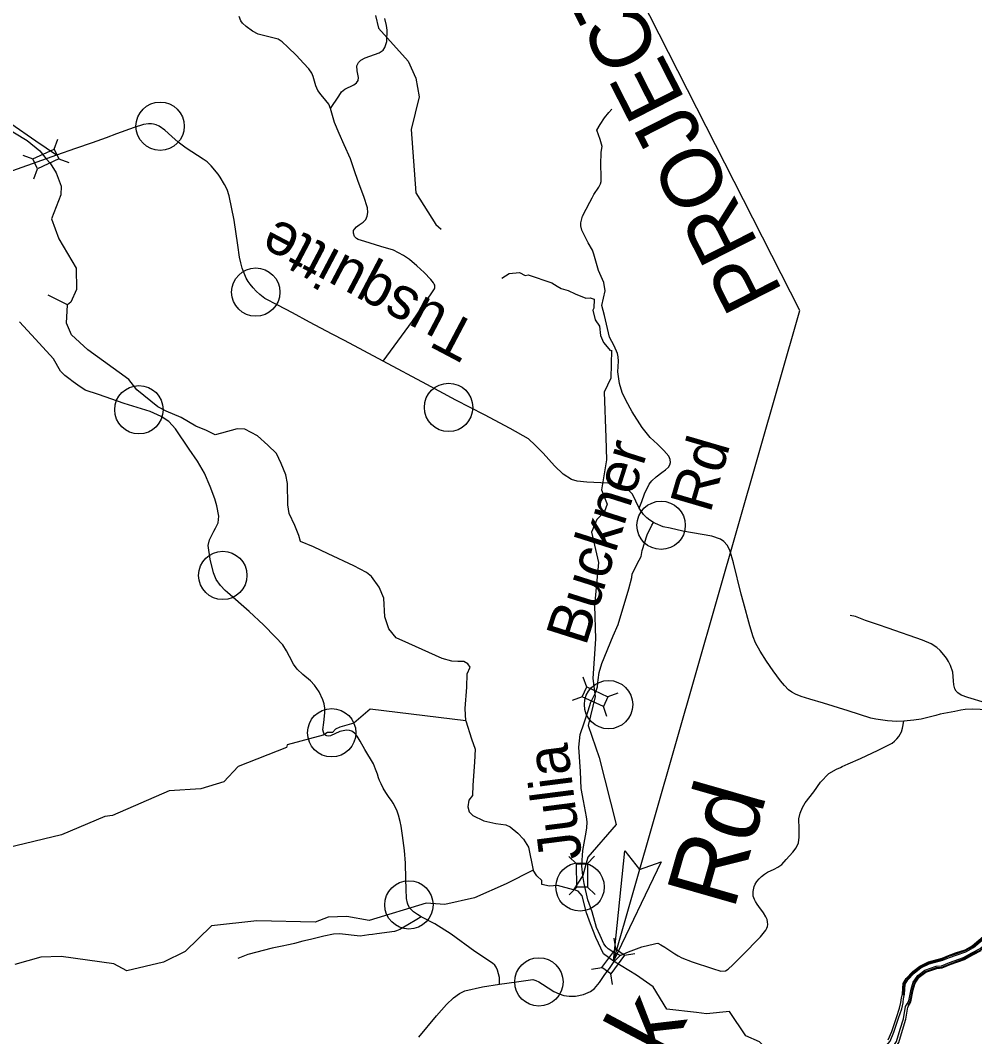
# Model space of a CAD drawing. Extents: x 558484 to 564063, y 513718 to 518374.
# Drawn here: x 559306.6 to 559464.9, y 514849.4 to 515017.9 of the extents above; entities that cross this region are included whole.
import ezdxf

# ---------------------------------------------------------------- set-up
doc = ezdxf.new("R2010")
doc.units = 0
for name, color, linetype in [('Default', 7, 'Continuous'), ('Prop Shade Heavy', 7, 'Continuous'), ('Prop Terminator CELL', 7, 'Continuous')]:
    doc.layers.add(name, color=color, linetype=linetype)

msp = doc.modelspace()

# ---------------------------------------------------------------- linework, layer by layer
at = {"layer": 'Default'}
for p, q in [((559312.23, 514996.58), (559312.84, 514998.24)), ((559312.6, 514995.58), (559298.66, 514990.63)), ((559307.06, 514995.55), (559308.72, 514994.94)), ((559312.98, 514994.97), (559314.64, 514994.37)), ((559308.88, 514991.64), (559309.49, 514993.31)), ((559314.47, 514970.78), (559311.23, 514972.37)), ((559400.56, 514907.37), (559399.95, 514909.03)), ((559399.81, 514905.77), (559398.15, 514905.16)), ((559405.74, 514906.37), (559404.08, 514905.77)), ((559403.92, 514902.47), (559403.32, 514904.13)), ((559398.86, 514878.05), (559397.59, 514879.29)), ((559400.63, 514878.07), (559401.86, 514879.34)), ((559399.9, 514876.13), (559398.36, 514873.77)), ((559397.66, 514872.91), (559398.89, 514874.18)), ((559401.97, 514872.96), (559400.7, 514874.2)), ((559405.38, 514864), (559405.11, 514865.75)), ((559406.81, 514862.95), (559408.56, 514863.22)), ((559401.34, 514860.61), (559403.09, 514860.88)), ((559404.81, 514858.06), (559404.55, 514859.81))]:
    msp.add_line(p, q, dxfattribs=at)
for points in [[(559358.09, 515003.29), (559357.81, 515004), (559357.3, 515004.65), (559356.54, 515005.55), (559355.95, 515006.27), (559355.61, 515007.04), (559355.18, 515008.59), (559354.94, 515009.18), (559354.48, 515009.9), (559353.61, 515010.84), (559352.41, 515012.1), (559351, 515013.48), (559350.05, 515014.35), (559349.36, 515014.79), (559346.05, 515015.65), (559345.15, 515016.12), (559344.1, 515016.89), (559343.45, 515017.44), (559343.18, 515017.86), (559342.91, 515018.58)], [(559365.55, 515018.72), (559366.04, 515016.65), (559370.93, 515011.14), (559372.24, 515008.31), (559372.75, 515005.26), (559371.45, 514999.82), (559372.21, 514989.32), (559375.53, 514984.1), (559376.41, 514983.31)], [(559295.85, 515017.9), (559296.77, 515015.43), (559296.56, 515011.17), (559296.9, 515009.3), (559297.78, 515007.14), (559298.85, 515005.69), (559303.22, 515000.72), (559307.74, 514998.01), (559309.87, 514996.27), (559310.89, 514994.94)], [(559358.09, 515003.29), (559359.42, 515005.34), (559359.87, 515006.08), (559360.45, 515006.5), (559361.95, 515007.25), (559362.4, 515007.56), (559362.67, 515007.95), (559362.69, 515008.45), (559362.48, 515009.53), (559362.44, 515010.36), (559362.68, 515010.93), (559363.12, 515011.32), (559363.83, 515011.71), (559366.11, 515012.53), (559366.77, 515012.99), (559367.06, 515013.42), (559367.38, 515014.41), (559367.46, 515016.32), (559367.34, 515017.06), (559367.05, 515018.25)], [(559366.81, 514961.41), (559371.68, 514968.03), (559374.89, 514972.77), (559375.29, 514973.43), (559375.35, 514973.59), (559375.38, 514973.74), (559375.38, 514973.88), (559375.36, 514974.03), (559375.28, 514974.2), (559375.17, 514974.4), (559374.7, 514974.98), (559373.6, 514976.1), (559372.39, 514977.22), (559371.16, 514978.25), (559370.19, 514978.95), (559368.49, 514979.83), (559366.39, 514980.45), (559363.74, 514981.24), (559362.66, 514981.6), (559362.35, 514981.76), (559362.06, 514982.08), (559361.86, 514982.65), (559361.9, 514983.08), (559362.03, 514983.31), (559362.36, 514983.66), (559362.82, 514984), (559363.5, 514984.46), (559363.91, 514984.9), (559364.15, 514985.43), (559364.24, 514986.04), (559364.19, 514986.84), (559363.59, 514988.74), (559362.63, 514991.2), (559361.98, 514993.16), (559361.37, 514994.95), (559360.35, 514997.28), (559359.52, 514999.14), (559358.72, 515001), (559358.09, 515003.29)], [(559401.45, 514988.51), (559401.73, 514989.07), (559402.58, 514990.25), (559402.87, 514990.81), (559402.94, 514991.2), (559402.93, 514992.09), (559402.88, 514993.98), (559402.93, 514996.09), (559403.1, 514997.01), (559402.79, 514998.19), (559402.23, 514999.71), (559402.78, 515000.63), (559403.49, 515001.74), (559404.2, 515002.62), (559404.7, 515003.22)], [(559312.6, 514995.58), (559309.17, 514997.9), (559305.04, 515000.79)], [(559366.81, 514961.41), (559360.37, 514964.86), (559358.32, 514965.91), (559354.56, 514967.89), (559351.77, 514969.41), (559349.34, 514970.7), (559347.17, 514971.82), (559346.35, 514972.47), (559345.75, 514973), (559345.25, 514973.56), (559344.74, 514974.16), (559344.41, 514974.61), (559344.08, 514975.16), (559343.87, 514975.71), (559343.41, 514976.81), (559343.18, 514977.7), (559342.97, 514978.68), (559342.68, 514980.65), (559342.09, 514984.77), (559341.27, 514988.84), (559340.91, 514989.86), (559340.47, 514990.7), (559339.79, 514991.92), (559339.42, 514992.43), (559338.26, 514993.81), (559337.6, 514994.44), (559336.95, 514994.93), (559334.14, 514996.73), (559332.82, 514997.71), (559331.73, 514998.69), (559330.57, 514999.74), (559329.65, 515000.37), (559329.13, 515000.61), (559328.7, 515000.73), (559328.36, 515000.78), (559327.88, 515000.74), (559327.06, 515000.64), (559325.51, 515000.18), (559322.55, 514999.09), (559320.84, 514998.47), (559318.51, 514997.64), (559315.78, 514996.65), (559312.6, 514995.58)], [(559310.89, 514994.94), (559311.58, 514994.25), (559312.58, 514992.64), (559313.42, 514990.42), (559313.36, 514988.99), (559311.78, 514985.01), (559312.98, 514981.68), (559315.87, 514976.83), (559315.93, 514973.29), (559315.02, 514971.17), (559314.47, 514970.78)], [(559409.28, 514937.06), (559409.69, 514938.12), (559410.13, 514939.44), (559410.94, 514941), (559411.38, 514941.55), (559412.06, 514942.23), (559412.99, 514942.93), (559413.64, 514943.4), (559414.11, 514943.84), (559414.32, 514944.2), (559414.43, 514944.6), (559414.38, 514945.11), (559414.15, 514945.67), (559413.37, 514946.6), (559412.27, 514947.63), (559411.1, 514948.76), (559409.77, 514950.44), (559408.11, 514953), (559407.05, 514954.92), (559406.42, 514956.22), (559405.97, 514957.73), (559405.71, 514959.65), (559405.82, 514961.44), (559405.8, 514962.15), (559405.66, 514962.67), (559405.09, 514963.96), (559404.32, 514965.4), (559403.49, 514968.96), (559403.07, 514970.64), (559403.59, 514973.09), (559403.41, 514974.47), (559402.53, 514976.44), (559401.72, 514979.15), (559401.51, 514979.84), (559400.77, 514981.05), (559399.72, 514983.12), (559399.56, 514983.85), (559399.6, 514984.37), (559399.86, 514985.46), (559401.09, 514987.79), (559401.45, 514988.51)], [(559386.49, 514975.15), (559387.71, 514975.95), (559389.4, 514976.09), (559390.33, 514975.63), (559390.82, 514975.74), (559394.79, 514974.38), (559395.65, 514973.85), (559396.31, 514973.46), (559397.47, 514973.14), (559398.62, 514972.59), (559400.41, 514971.86), (559401.12, 514971.92), (559401.77, 514971.68), (559401.74, 514970.22), (559401.55, 514969.85), (559401.98, 514968.26), (559402.69, 514967.21), (559402.86, 514965.67), (559403.32, 514964.49), (559404.48, 514963.15)], [(559325.96, 514956.68), (559324.63, 514958.37), (559317.81, 514963.29), (559315.12, 514965.79), (559314.3, 514967.71), (559314.47, 514970.78)], [(559350.79, 514913.4), (559350.13, 514914.38), (559348.96, 514915.64), (559346.93, 514917.72), (559344.56, 514919.89), (559340.97, 514923.05), (559340.57, 514923.39), (559339.82, 514924.22), (559339.11, 514925.2), (559338.67, 514926.34), (559338.1, 514928.59), (559337.79, 514930.87), (559338.02, 514931.81), (559338.72, 514933.23), (559339, 514933.73), (559339.44, 514934.63), (559339.53, 514935.7), (559339.21, 514937.45), (559338.89, 514938.57), (559338.08, 514940.64), (559337.16, 514942.87), (559335.99, 514944.81), (559334.62, 514946.81), (559332.33, 514950.19), (559331.24, 514951.43), (559330, 514952.26), (559328.13, 514953.09), (559323.83, 514954.37), (559319.6, 514955.91), (559317.36, 514956.63), (559316.18, 514957.43), (559315.38, 514958.01), (559314.69, 514958.53), (559313.99, 514959.06), (559313.28, 514959.76), (559312.11, 514961.78), (559310.37, 514963.76), (559308.46, 514965.79), (559306.51, 514967.92)], [(559404.68, 514963.22), (559404.54, 514958.62), (559403.46, 514956.28), (559403.71, 514948.78), (559403.83, 514945.03), (559403.03, 514940.1), (559403.97, 514937.68), (559403.53, 514936.48), (559402.23, 514935.18), (559401.36, 514933.08), (559402.5, 514928.02), (559401.86, 514920.88), (559402.01, 514915.39), (559401.57, 514908.77), (559401.94, 514905.84), (559400.78, 514901), (559402.63, 514895.7), (559405.43, 514884.57), (559400.76, 514879.15), (559399.9, 514876.13)], [(559409.28, 514937.06), (559408.14, 514939.35), (559407.32, 514940.2), (559406.67, 514940.66), (559405.5, 514941.1), (559404.06, 514941.19), (559400.56, 514941.33), (559398.98, 514941.54), (559398.01, 514941.8), (559396.67, 514942.66), (559395.2, 514944.05), (559393.35, 514946.15), (559392, 514947.49), (559390.88, 514948.52), (559387.87, 514950.24), (559383.6, 514952.51), (559378.83, 514954.94), (559374.05, 514957.54), (559366.81, 514961.41)], [(559355.27, 514930.65), (559353.11, 514931.54), (559352.8, 514932.49), (559352.14, 514934.14), (559351.22, 514936.16), (559350.99, 514937.58), (559350.93, 514941.12), (559350.65, 514942.58), (559349.89, 514944.43), (559349.08, 514946.08), (559347.68, 514947.5), (559345.96, 514949.01), (559343.88, 514950.15), (559342.57, 514950.2), (559339.96, 514949.47), (559338.95, 514949.21), (559337.48, 514949.9), (559335.75, 514950.64), (559333.32, 514952.1), (559330.81, 514953.12), (559329.45, 514953.83), (559325.96, 514956.68)], [(559411.65, 514934.68), (559411.01, 514935.06), (559410.51, 514935.42), (559409.99, 514936), (559409.28, 514937.06)], [(559403.05, 514911.28), (559404.97, 514915.89), (559405.75, 514917.75), (559407.54, 514923.68), (559408.02, 514925.54), (559408.11, 514926.16), (559409.26, 514928.41), (559409.57, 514929.05), (559409.77, 514930.04), (559410.56, 514932.63), (559411.38, 514934.21), (559411.65, 514934.68)], [(559453.14, 514901.73), (559452, 514901.67), (559450.42, 514901.77), (559448.49, 514902.07), (559447.68, 514902.22), (559443.9, 514903.43), (559439.83, 514904.7), (559437.57, 514905.39), (559436.11, 514905.81), (559435.2, 514906.19), (559434.6, 514906.52), (559434.03, 514906.93), (559433.34, 514907.63), (559432.71, 514908.42), (559431.5, 514910.07), (559430.38, 514911.69), (559429.31, 514913.32), (559428.55, 514914.69), (559428.18, 514915.71), (559427.62, 514917.54), (559426.54, 514921.41), (559426.2, 514922.76), (559424.91, 514927.96), (559424.28, 514930.07), (559423.84, 514930.92), (559423.32, 514931.53), (559422.76, 514931.91), (559421.33, 514932.37), (559416.51, 514933.24), (559414.38, 514933.71), (559413.24, 514933.95), (559411.94, 514934.48), (559411.65, 514934.68)], [(559380.53, 514901.79), (559380.37, 514903.84), (559380.65, 514907.35), (559380.72, 514909.59), (559381.24, 514910.67), (559380.84, 514911.25), (559380.2, 514911.6), (559379.16, 514911.6), (559378.17, 514911.67), (559376.56, 514912.09), (559371.05, 514914.61), (559368.93, 514915.55), (559367.72, 514917.03), (559367.06, 514919.01), (559366.89, 514922.09), (559366.16, 514923.94), (559364.87, 514925.7), (559364.01, 514926.4), (559361.91, 514927.46), (559357.67, 514929.49), (559355.27, 514930.65)], [(559450.58, 514917.17), (559448.94, 514917.69), (559446.78, 514918.43), (559445.16, 514919.06), (559444.26, 514919.25)], [(559461.29, 514909.84), (559460.88, 514910.95), (559460.58, 514911.6), (559460.21, 514912.19), (559459.81, 514912.72), (559459.16, 514913.44), (559458.6, 514913.96), (559457.71, 514914.56), (559456.24, 514915.17), (559450.58, 514917.17)], [(559373.12, 514869.28), (559372.47, 514869.65), (559371.83, 514870.09), (559371.44, 514870.47), (559371.3, 514870.64), (559371.17, 514870.85), (559370.97, 514871.22), (559370.82, 514871.56), (559370.68, 514872.34), (559370.62, 514873.86), (559370.58, 514875.57), (559370.5, 514878.16), (559370.35, 514880.29), (559370.02, 514882.77), (559369.76, 514884.31), (559369.6, 514885.09), (559369.36, 514886.16), (559369.07, 514886.99), (559368.45, 514888.15), (559368.16, 514888.59), (559367.81, 514889.07), (559367.26, 514889.89), (559366.8, 514890.62), (559366.46, 514891.31), (559366.19, 514891.87), (559366.04, 514892.31), (559365.83, 514892.92), (559365.55, 514893.75), (559365.17, 514894.66), (559363.78, 514897.04), (559362.97, 514898.39), (559362.46, 514899.23), (559362.02, 514899.74), (559361.6, 514900.06), (559361.22, 514900.19), (559360.71, 514900.21), (559359.63, 514900), (559358.06, 514899.3), (559357.66, 514899.24), (559357.44, 514899.3), (559357.29, 514899.35), (559357.03, 514899.58), (559356.89, 514899.9), (559356.81, 514900.3), (559356.97, 514901.48), (559357.14, 514903.11), (559357.15, 514903.88), (559357.03, 514904.61), (559356.8, 514905.25), (559356.18, 514906.56), (559355.43, 514907.71), (559354.76, 514908.4), (559353.45, 514909.45), (559352.52, 514910.36), (559351.9, 514911.17), (559351.26, 514912.44), (559350.79, 514913.4)], [(559401.95, 514906.31), (559402.15, 514906.73), (559402.34, 514907.4), (559402.39, 514908.12), (559402.45, 514908.6), (559402.63, 514909.78), (559403.05, 514911.28)], [(559470.23, 514903.08), (559469.47, 514903.71), (559468.53, 514904.21), (559466.67, 514904.78), (559463.79, 514905.66), (559462.65, 514906.06), (559462.11, 514906.4), (559461.83, 514906.67), (559461.61, 514907.06), (559461.47, 514907.73), (559461.39, 514908.43), (559461.29, 514909.84)], [(559399.74, 514877.83), (559399.94, 514880.26), (559400.38, 514882.71), (559400.55, 514883.97), (559400.65, 514885.01), (559400.54, 514885.87), (559400, 514888.5), (559399.64, 514890.58), (559399.53, 514893.37), (559399.27, 514897.41), (559399.49, 514899.51), (559400.16, 514901.46), (559400.8, 514903.43), (559401.23, 514904.85), (559401.95, 514906.31)], [(559380.53, 514901.79), (559364.63, 514903.72), (559361.93, 514901.41), (559359.63, 514900.73), (559358.87, 514900.4), (559358.39, 514899.87), (559357.59, 514899.85), (559356.83, 514899.41), (559350.86, 514897.82), (559350.75, 514897.34), (559342.77, 514894.18), (559340.35, 514891.66), (559336.57, 514890.53), (559331.29, 514890.16), (559321.88, 514886.07), (559320.64, 514885.94), (559313.47, 514882.86), (559301.23, 514879.93)], [(559470.23, 514903.08), (559467.54, 514903.45), (559465.81, 514903.67), (559464.6, 514903.71), (559463.34, 514903.63), (559462.59, 514903.54), (559461.6, 514903.34), (559459.18, 514902.86), (559458.46, 514902.69)], [(559458.46, 514902.69), (559456.01, 514902.07), (559454.8, 514901.9), (559453.14, 514901.73)], [(559380.53, 514901.79), (559381.46, 514898.78), (559382.07, 514897.08), (559381.92, 514894.94), (559381.66, 514891.12), (559381.62, 514889.38), (559381, 514888.64), (559380.86, 514887.5), (559381.05, 514886.71), (559381.68, 514886.08), (559383.47, 514885.18), (559385.47, 514884.75), (559387.12, 514884.52), (559387.88, 514884.2), (559389.13, 514883.16), (559390.07, 514882.14), (559390.89, 514880.82), (559391.69, 514877.01)], [(559440.71, 514893.07), (559442, 514893.76), (559442.62, 514894.05), (559442.94, 514894.2), (559443.91, 514894.66), (559445.95, 514895.54), (559448.91, 514896.93), (559451.19, 514898.09), (559451.61, 514898.4), (559452, 514898.78), (559452.3, 514899.17), (559452.57, 514899.59), (559452.74, 514899.97), (559452.91, 514900.54), (559453.14, 514901.73)], [(559435.74, 514885.51), (559435.96, 514886.47), (559436.33, 514887.39), (559436.76, 514888.16), (559438.2, 514890.01), (559439.33, 514891.63), (559440.71, 514893.07)], [(559406.13, 514862.89), (559407.46, 514863.49), (559409.72, 514864.28), (559411.8, 514864.82), (559412, 514864.87), (559412.37, 514864.89), (559412.86, 514864.65), (559413.5, 514864.24), (559415.15, 514863.17), (559415.73, 514862.82), (559416.35, 514862.5), (559418.03, 514861.81), (559421.41, 514860.7), (559422.78, 514860.29), (559423.57, 514860.35), (559424, 514860.61), (559424.8, 514861.33), (559426.26, 514862.83), (559429.39, 514865.98), (559430.06, 514866.79), (559430.27, 514867.07), (559430.42, 514867.42), (559430.53, 514867.69), (559430.6, 514868.03), (559430.56, 514868.44), (559430.47, 514868.83), (559430.28, 514869.29), (559429.85, 514869.93), (559429.1, 514870.98), (559428.83, 514871.38), (559428.57, 514871.82), (559428.37, 514872.18), (559428.19, 514872.68), (559428.15, 514873.1), (559428.16, 514873.5), (559428.34, 514874.29), (559428.49, 514874.68), (559428.76, 514875.15), (559429.17, 514875.6), (559429.55, 514875.95), (559430.02, 514876.35), (559430.53, 514876.68), (559431.63, 514877.2), (559432.27, 514877.51), (559432.6, 514877.71), (559432.94, 514877.98), (559433.65, 514878.76), (559434.73, 514879.99), (559435.31, 514880.74), (559435.66, 514881.55), (559435.77, 514882.48), (559435.8, 514883.86), (559435.74, 514885.51)], [(559453.72, 514854.86), (559453.98, 514855.33), (559454.36, 514857.27), (559454.69, 514858.43), (559455.46, 514859.54), (559456.64, 514860.41), (559458.54, 514861.1), (559459.41, 514861.16), (559460.72, 514861.71), (559463.05, 514862.56), (559464.41, 514863.32), (559465.79, 514864.02), (559467.1, 514865.07), (559468.32, 514866.08), (559469.02, 514867.24), (559470.68, 514869.95), (559471.55, 514871.19), (559472.17, 514872.07), (559472.68, 514873.63), (559473.7, 514876.25), (559474.41, 514878.71), (559474.73, 514880), (559475.19, 514881.12), (559475.52, 514882.47)], [(559453.86, 514854.63), (559454.2, 514855.25), (559454.58, 514857.22), (559454.9, 514858.34), (559455.62, 514859.38), (559456.75, 514860.2), (559458.59, 514860.87), (559459.46, 514860.93), (559460.81, 514861.5), (559463.14, 514862.35), (559464.51, 514863.12), (559465.91, 514863.83), (559467.25, 514864.9), (559468.5, 514865.93), (559469.22, 514867.12), (559470.87, 514869.83), (559471.74, 514871.06), (559472.37, 514871.97), (559472.89, 514873.55), (559473.92, 514876.18), (559474.63, 514878.65), (559474.95, 514879.92), (559475.41, 514881.05), (559475.74, 514882.41)], [(559391.69, 514877.01), (559387.18, 514874.76), (559381.94, 514872.41), (559377, 514871.32), (559373.95, 514871.52), (559364.5, 514868.7), (559360.78, 514869.31), (559357.7, 514869.21), (559355.54, 514868.39), (559345.87, 514868.6), (559338.35, 514867.79), (559333.98, 514863.54), (559330.39, 514861.79), (559324.31, 514860.34), (559322.11, 514861.49), (559313.38, 514862.7), (559310.01, 514862.61), (559305.7, 514861.39)], [(559398.36, 514873.77), (559395.7, 514874.5), (559394.36, 514874.35), (559393.11, 514874.64), (559393.12, 514875.32), (559392.3, 514876.08), (559391.69, 514877.01)], [(559399.9, 514876.13), (559399.73, 514877.7), (559399.74, 514877.83)], [(559406.13, 514862.89), (559404.91, 514863.5), (559404.11, 514863.96), (559403.76, 514864.28), (559403.39, 514864.8), (559402.8, 514866.17), (559402.18, 514867.53), (559401.47, 514870.09), (559400.72, 514872.1), (559400.15, 514874.83), (559399.9, 514876.13)], [(559438.04, 514840.42), (559434.6, 514842.86), (559429.22, 514848.57), (559426.93, 514849.54), (559424.22, 514853.6), (559420.44, 514853.19), (559418.74, 514853.42), (559413.82, 514853.95), (559411.59, 514857.68), (559408.83, 514859.59), (559405, 514861.93), (559403.35, 514863.12), (559402.06, 514865.88), (559401.2, 514868.14), (559400.51, 514869.94), (559399.78, 514872.78), (559399.14, 514873.55), (559398.35, 514873.79)], [(559373.12, 514869.28), (559372.39, 514868.84), (559370.91, 514867.94), (559369.54, 514867.17), (559368.99, 514866.94), (559368.65, 514866.86), (559365.75, 514866.44), (559365.05, 514866.37), (559364.42, 514866.27), (559362.96, 514866.1), (559359.57, 514866.48), (559358.57, 514866.41), (559356.97, 514866.09), (559355.65, 514865.77), (559354.72, 514865.53), (559353.47, 514865.23), (559352.11, 514864.86), (559351.36, 514864.71), (559349.78, 514864.37), (559348.39, 514864.06), (559344.33, 514863.03), (559342.71, 514862.38)], [(559386.07, 514858.11), (559386.08, 514859.24), (559385.76, 514860.43), (559385.56, 514860.91), (559385.3, 514861.27), (559384.93, 514861.6), (559382.02, 514863.54), (559378.1, 514866.4), (559375.34, 514868.12), (559373.12, 514869.28)], [(559450.56, 514848.87), (559451.16, 514850.26), (559451.91, 514852.61), (559452.45, 514854.13), (559452.68, 514855.07), (559452.76, 514855.86), (559452.92, 514856.51), (559453.04, 514858.23), (559453.55, 514859.07), (559454.64, 514860.2), (559455.79, 514861.11), (559457.25, 514861.81), (559459.51, 514862.42), (559460.58, 514862.89), (559461.73, 514863.29), (559463.31, 514863.83), (559464.48, 514864.47), (559466.69, 514866.36)], [(559453.03, 514856.3), (559453.07, 514856.48), (559453.19, 514858.19), (559453.67, 514858.97), (559454.74, 514860.09), (559455.88, 514860.97), (559457.31, 514861.67), (559459.56, 514862.27), (559460.63, 514862.75), (559461.78, 514863.14), (559463.37, 514863.69), (559464.57, 514864.34), (559466.79, 514866.24)], [(559453.15, 514855.94), (559453.28, 514856.45), (559453.39, 514858.12), (559453.83, 514858.85), (559454.88, 514859.93), (559455.98, 514860.8), (559457.38, 514861.47), (559459.63, 514862.08), (559460.71, 514862.56), (559461.85, 514862.95), (559463.46, 514863.5), (559464.68, 514864.18), (559466.93, 514866.09)], [(559451.1, 514846.95), (559451.84, 514847.68), (559452.31, 514848.44), (559452.95, 514850.51), (559453.48, 514852.3), (559453.83, 514854.3), (559454.33, 514855.2), (559454.71, 514857.19), (559455.02, 514858.28), (559455.72, 514859.28), (559456.81, 514860.08), (559458.61, 514860.74), (559459.49, 514860.8), (559460.86, 514861.37), (559463.2, 514862.23), (559464.58, 514863), (559465.98, 514863.72)], [(559386.07, 514858.11), (559388.89, 514858.52), (559391.64, 514858.9), (559392.11, 514858.72), (559392.62, 514858.49), (559393.25, 514858.09), (559395.13, 514856.92), (559395.97, 514856.53), (559396.75, 514856.24), (559397.63, 514856.13), (559398.72, 514856.15), (559400.05, 514856.41), (559401.18, 514856.92), (559401.84, 514857.4), (559402.69, 514858.41), (559403.58, 514859.72), (559404.32, 514860.7), (559405.13, 514861.87)], [(559405.13, 514861.87), (559405.48, 514862.27), (559406.13, 514862.89)], [(559372.71, 514849.31), (559375.62, 514852.89), (559377.32, 514854.75), (559378.49, 514855.85), (559379.46, 514856.59), (559380.34, 514857.03), (559383.28, 514857.66), (559386.07, 514858.11)], [(559438.33, 514840.14), (559439.81, 514841.31), (559440.98, 514842.11), (559443.09, 514842.96), (559445.67, 514843.83), (559446.87, 514844.66), (559448.27, 514845.79), (559449.57, 514847.14), (559450.87, 514848.67), (559451.5, 514850.13), (559452.25, 514852.5), (559452.8, 514854.03), (559453.04, 514855.01), (559453.11, 514855.8), (559453.15, 514855.94)], [(559450.62, 514847.29), (559451.52, 514847.94), (559451.93, 514848.62), (559452.56, 514850.63), (559453.07, 514852.39), (559453.43, 514854.44), (559453.72, 514854.86)]]:
    msp.add_lwpolyline(points, dxfattribs=at)
for points in [[(559308.72, 514994.94), (559312.23, 514996.58), (559313, 514994.95), (559309.49, 514993.31)], [(559403.32, 514904.13), (559399.81, 514905.76), (559400.57, 514907.4), (559404.08, 514905.77)], [(559398.89, 514874.18), (559398.85, 514878.05), (559400.66, 514878.07), (559400.7, 514874.2)], [(559403.09, 514860.88), (559405.38, 514864), (559406.84, 514862.93), (559404.55, 514859.81)]]:
    msp.add_lwpolyline(points, close=True, dxfattribs=at)
at = {"layer": 'Prop Shade Heavy'}
for p, q in [((559435.92, 514969.81), (559376.95, 515085.62)), ((559405, 514861.93), (559435.92, 514969.81))]:
    msp.add_line(p, q, dxfattribs=at)
for centre in [(559329.81, 515000.37), (559345.67, 514972.86), (559377.65, 514953.75), (559326.29, 514953.36), (559412.89, 514934.2), (559340.2, 514925.89), (559404.18, 514904.46), (559358.26, 514899.8), (559399.45, 514874.24), (559371.07, 514871.26), (559392.62, 514858.49)]:
    msp.add_circle(centre, 4.01, dxfattribs=at)
at = {"layer": 'Prop Terminator CELL'}
msp.add_lwpolyline([(559412.92, 514878.39), (559405, 514861.93), (559406.88, 514880.22), (559409.33, 514877.13)], close=True, dxfattribs=at)

# ---------------------------------------------------------------- texts
at = {"layer": 'Default'}
for s, height, rotation, p in [('Tusquitte', 7, 152.1931, (559382.96, 514967.3)), ('Buckner', 7.031, 72.364, (559400.39, 514914.02)), ('Rd', 7.031, 73.696, (559421.03, 514936.05)), ('Julia', 7.031, 97.273, (559399.79, 514879.04)), ('Rd', 11.719, 74.0074, (559424.93, 514870.21)), ('Creek', 11.719, 62.0399, (559397.72, 514815.34))]:
    msp.add_text(s, height=height, rotation=rotation, dxfattribs=at).set_placement(p)
at = {"layer": 'Prop Shade Heavy'}
msp.add_text('PROJECT LOCATION', height=10, rotation=116.9819, dxfattribs=at).set_placement((559433.18, 514972.9))

doc.saveas('drawing.dxf')
